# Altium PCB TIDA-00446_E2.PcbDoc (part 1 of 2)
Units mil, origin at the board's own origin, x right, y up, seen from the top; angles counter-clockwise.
Board outline 1780.03 x 5400.03 mil, 4 copper layers (Top Layer, GND, PWR, Bottom Layer), stack 79.834 mil thick; 192 components, 100 nets, 515 pads, 129 vias.
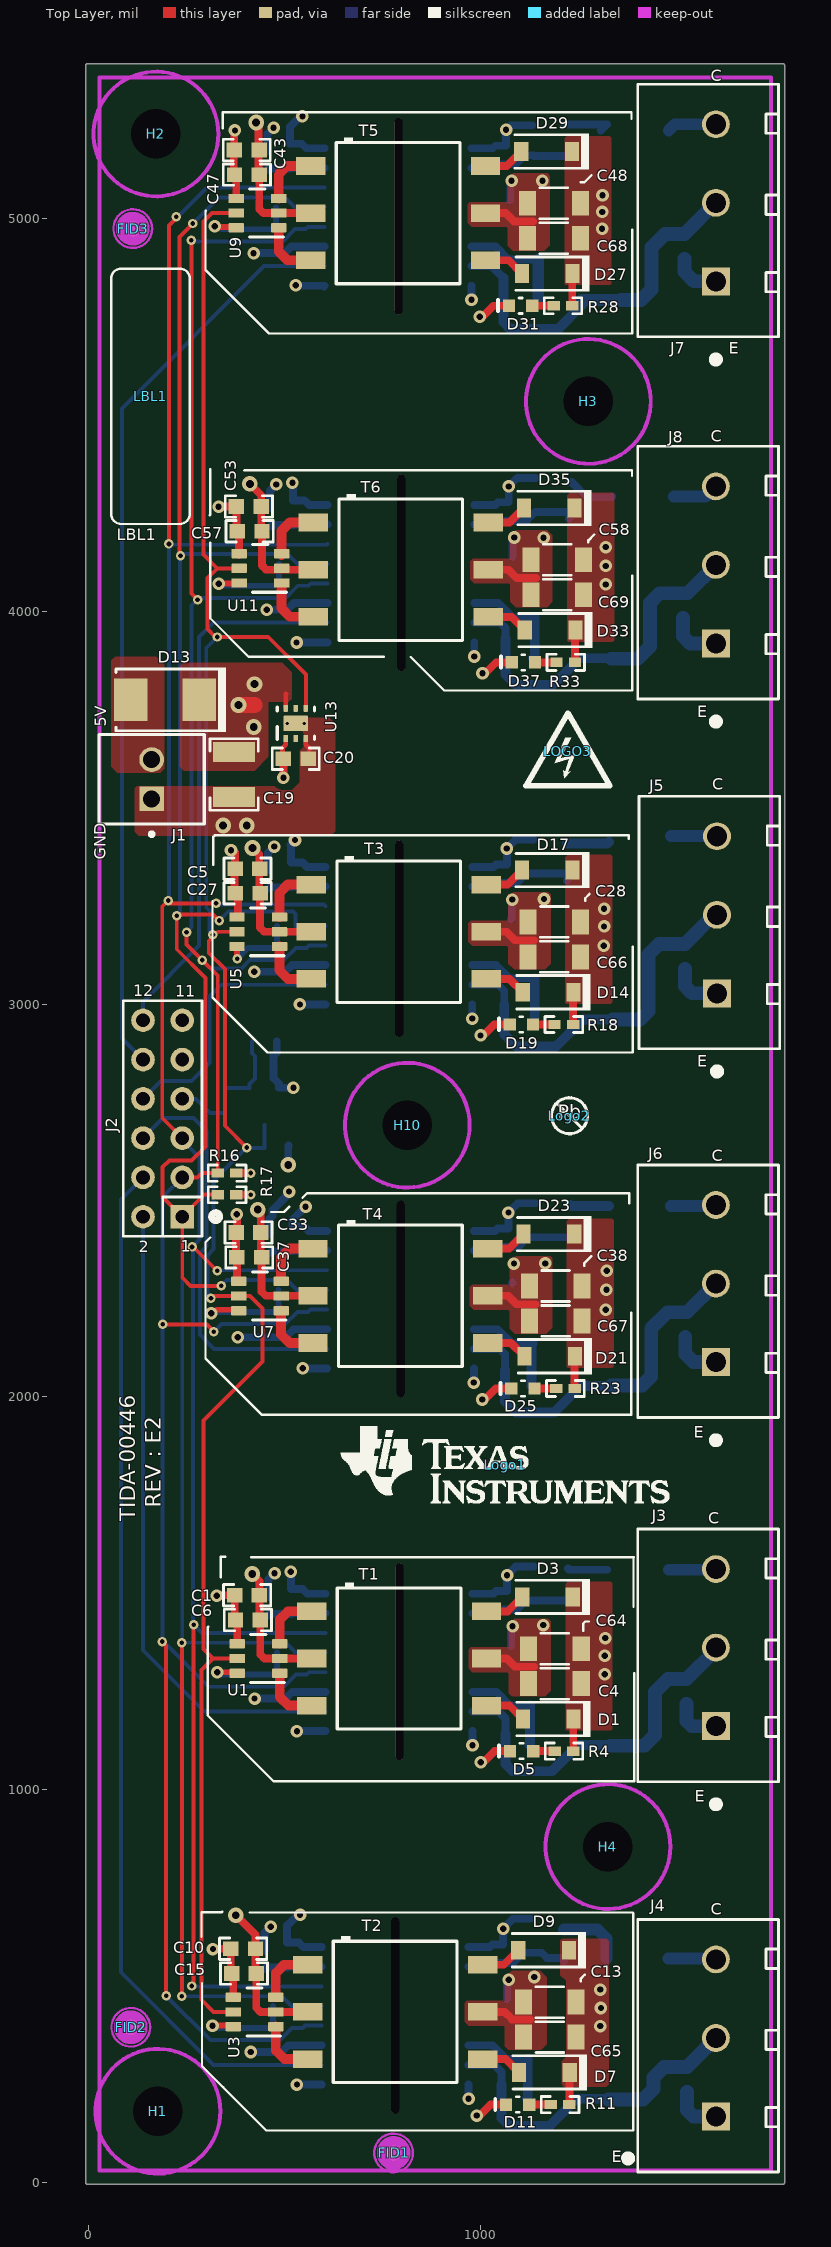
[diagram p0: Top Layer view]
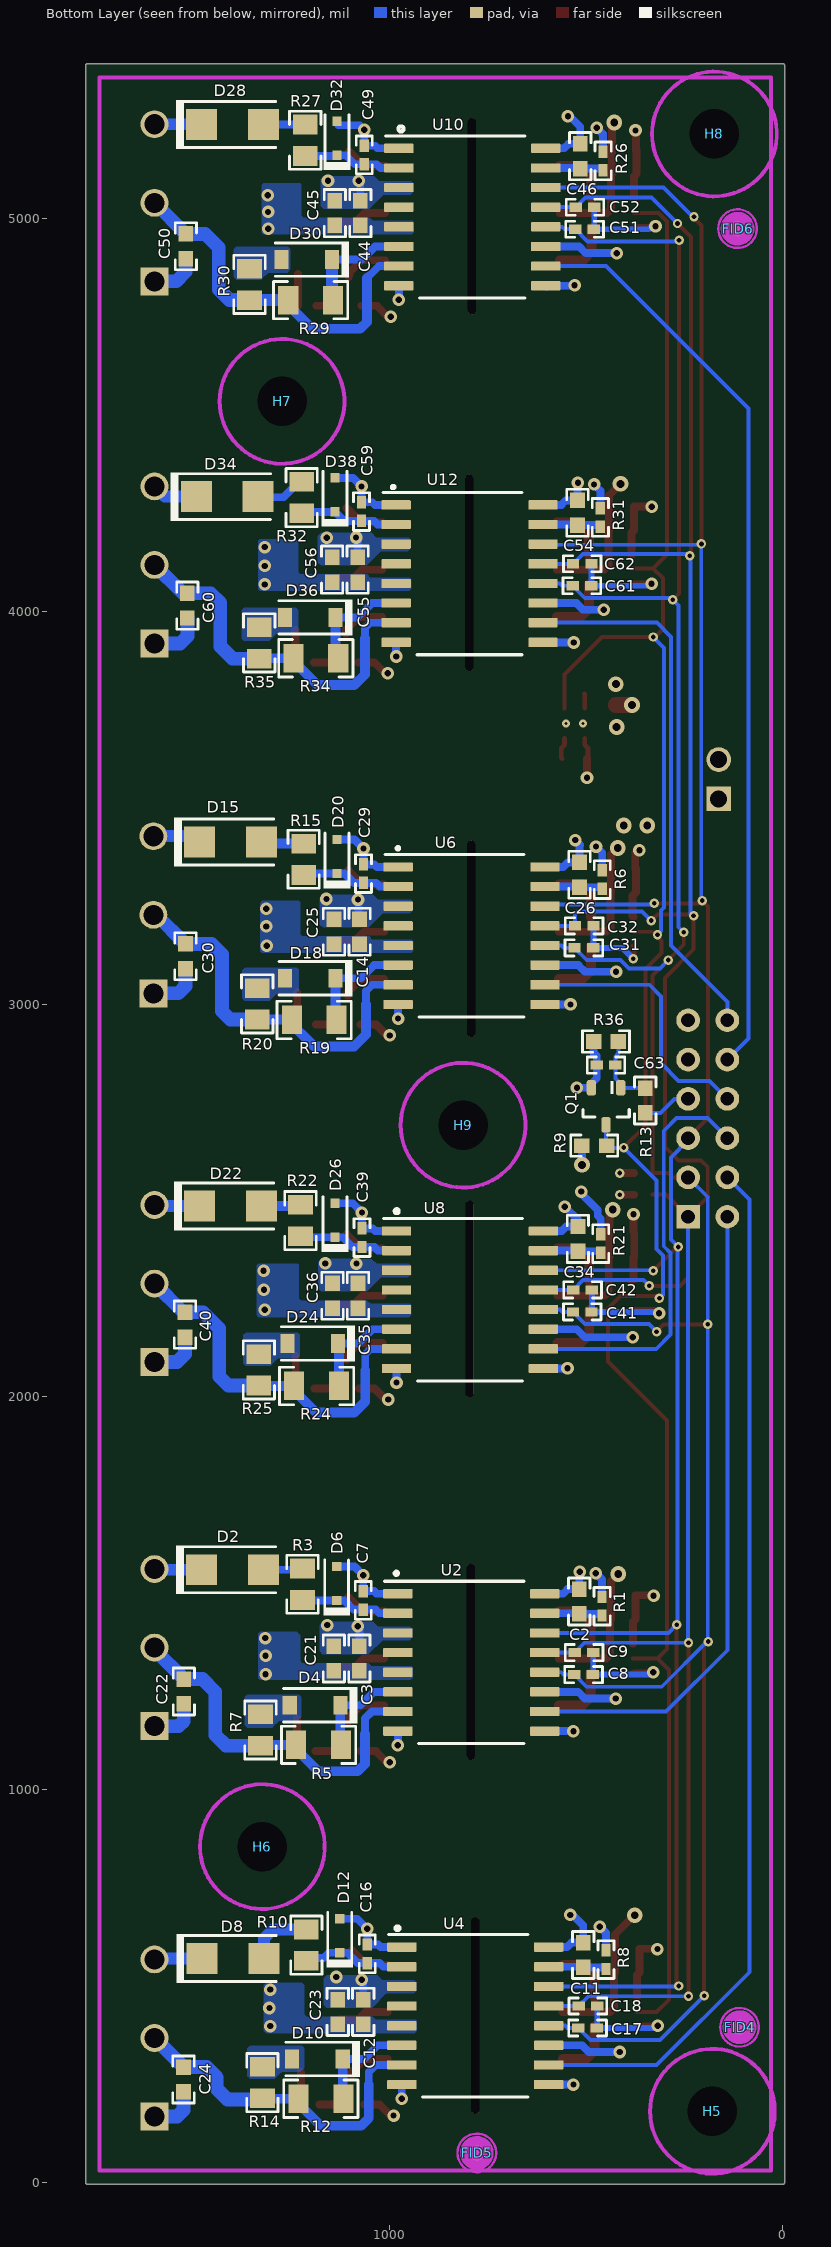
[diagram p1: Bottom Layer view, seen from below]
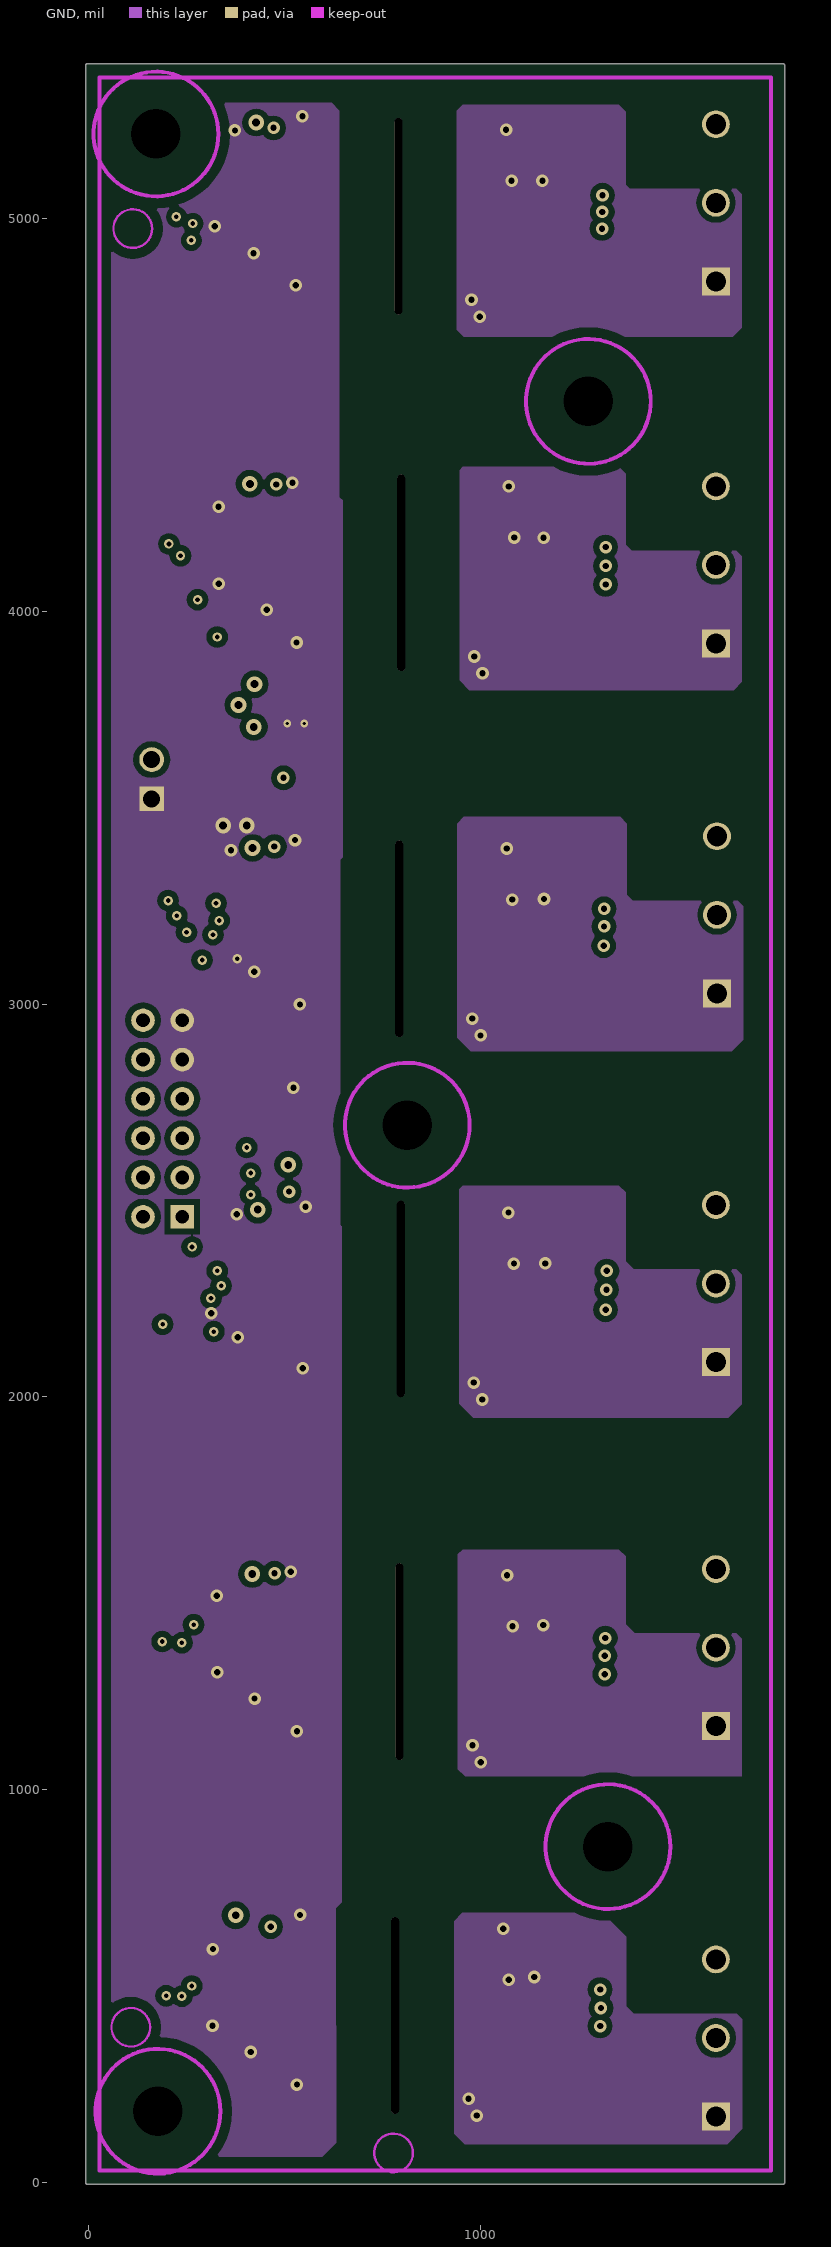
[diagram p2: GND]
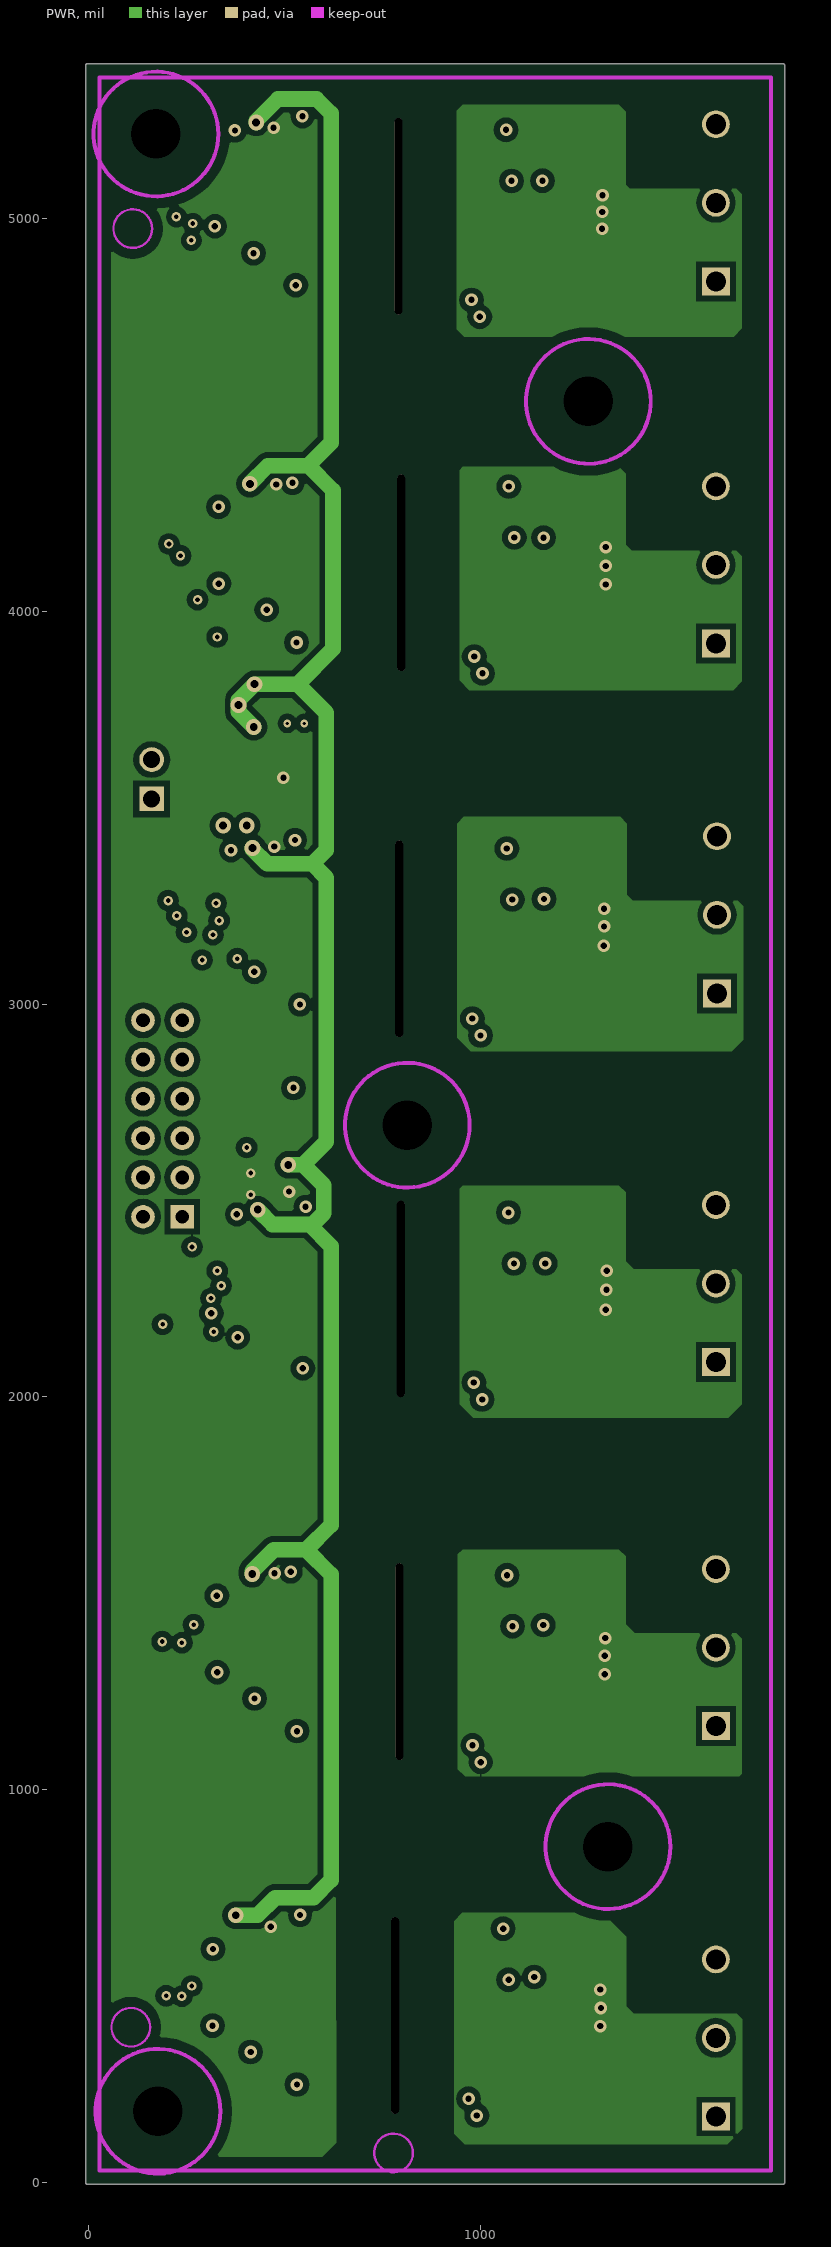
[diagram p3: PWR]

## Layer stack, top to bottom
Top Solder: solder mask 0.4, Solder Resist, Dk 3.5
Top Layer: signal copper 1.4
Dielectric1: core 59.2, FR-4, Dk 4.8
GND: signal copper 1.417
Dielectric2: prepreg 5, Dk 4.2
PWR: signal copper 1.417
Dielectric3: core 10, Dk 4.2
Bottom Layer: signal copper 1.4
Bottom Solder: solder mask 0.4, Solder Resist, Dk 3.5

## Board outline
-6.01,0 -6.01,5390 cw(c-1,5390) -1,5395.02 1769,5395.02 cw(c1769,5390) 1774.01,5390 1774.01,0 cw(c1769,0) 1769,-5.01 0,-5.01 cw(c0,0) -0.5,-4.99 cw(c-1,0)

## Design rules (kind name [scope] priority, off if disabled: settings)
AcuteAngle [All] p1: minimum=4.50000000000000E+0001 checktracksonly=FALSE
AssemblyTestPointUsage [All] p1: valid=2
Clearance Clearance_MTG_COPPER [InPadClass('MTG') vs InPolygon] p1: gap=40
Clearance Clearance_keepout [IsKeepOut vs InPolygon] p2: gap=25
Clearance "shape to all" [InPolygon] p3: gap=15
Clearance "Shape to Shape" [InPolygon vs InPolygon] p4: gap=20
Clearance Clearance_Boardedge_poly [OnCopper and InPolygon vs IsKeepOut] p5: gap=15
Clearance "SMD to Via" [IsSMTPin vs IsVia] p6: gap=8
Clearance "Clearance_via_thr pin" [IsVia vs IsThruPin] p7: gap=8
Clearance "Clearance_pad _class" [InPadClass('u12,u4,u5')] p8: gap=7.8
Clearance [All] p9: gap=8
DiffPairsRouting DiffPair_DiffPairsRouting [InDifferentialPair ('kan')] p1: maxlimit=10 minlimit=10 mostfreqgap=10 toplayer_minwidth=15 toplayer_maxwidth=15 toplayer_prefwidth=15 midlayer1_minwidth=15 midlayer1_maxwidth=15 midlayer1_prefwidth=15 midlayer2_minwidth=15 midlayer2_maxwidth=15 midlayer2_prefwidth=15 bottomlayer_minwidth=15 bottomlayer_maxwidth=15 bottomlayer_prefwidth=15 maxuncoupledlength=500
DiffPairsRouting DiffPair_DiffPairsRouting_1 [InDifferentialPair ('kan')] p2: maxlimit=10 minlimit=10 mostfreqgap=10 toplayer_minwidth=15 toplayer_maxwidth=15 toplayer_prefwidth=15 midlayer1_minwidth=15 midlayer1_maxwidth=15 midlayer1_prefwidth=15 midlayer2_minwidth=15 midlayer2_maxwidth=15 midlayer2_prefwidth=15 bottomlayer_minwidth=15 bottomlayer_maxwidth=15 bottomlayer_prefwidth=15 maxuncoupledlength=500
DiffPairsRouting [All] p3: maxlimit=100 minlimit=10 mostfreqgap=10 toplayer_minwidth=15 toplayer_maxwidth=15 toplayer_prefwidth=15 midlayer1_minwidth=15 midlayer1_maxwidth=15 midlayer1_prefwidth=15 midlayer2_minwidth=15 midlayer2_maxwidth=15 midlayer2_prefwidth=15 bottomlayer_minwidth=15 bottomlayer_maxwidth=15 bottomlayer_prefwidth=15 maxuncoupledlength=1000
FabricationTestPointUsage TestPointUsage [All] p1: valid=2 allowmultiple=FALSE
FabricationTestpoint Testpoint [All] p1: side=3 testpointundercomponent=TRUE minsize=40 maxsize=100 preferedsize=60 minholesize=0 maxholesize=40 preferedholesize=32 testpointgrid=1 allowsidetop=TRUE allowsidebottom=TRUE usegrid=TRUE gridtolerance=0.01
FanoutControl Fanout_LCC [IsLCC] p1: bgadir=Out bgaviamode=Centered fanoutstyle=Auto fanoutdirection=Alternating viagrid=1 // Fanout_LCC (Default Rule)
FanoutControl Fanout_BGA [IsBGA] p2: bgadir=Out bgaviamode=Centered fanoutstyle=Auto fanoutdirection=Alternating viagrid=1 // Fanout_BGA (Default Rule)
FanoutControl Fanout_Default [All] p4: bgadir=Out bgaviamode=Centered fanoutstyle=Auto fanoutdirection=Alternating viagrid=1 // Fanout_Default (Default Rule)
FanoutControl Fanout_Small [(CompPinCount < 5)] p5: bgadir=Out bgaviamode=Centered fanoutstyle=Auto fanoutdirection=OutThenIn viagrid=1 // Fanout_Small (Default Rule)
HoleSize [All] p1: absolutevalues=TRUE maxlimit=500 minlimit=7 maxpercent=80.000 minpercent=20.000
MatchedLengths DiffPair_MatchedLengths [InDifferentialPair ('kan')] p1: tolerance=1000 checknetsindiffpair=TRUE checkdiffpairvsdiffpair=TRUE checkothers=TRUE
MatchedLengths DiffPair_MatchedLengths_1 [InDifferentialPair ('kan')] p2: tolerance=1000 checknetsindiffpair=TRUE checkdiffpairvsdiffpair=TRUE checkothers=TRUE
MinimumAnnularRing [All] p1: minimumring=5
MinimumAnnularRing MinimumAnnularRing_ThermalPadVias [IsVia and InAnyComponent] p2: minimumring=5.91
MinimumSolderMaskSliver MinimumSolderMaskSliver_Logo [InComponentClass('Logo') vs InComponentClass('Logo')] p1: minsoldermaskwidth=0.7
MinimumSolderMaskSliver [All] p2: minsoldermaskwidth=3.94
PlaneClearance [All] p1: clearance=15
PlaneConnect [All] p1: planeconnectstyle=Direct reliefexpansion=10 reliefentries=4 reliefconductorwidth=10 reliefairgap=10
PolygonConnect [All] p1: connectstyle=Direct reliefconductorwidth=10 reliefentries=4 polygonreliefangle="90 Angle" airgapwidth=10
RoutingVias RoutingVias_power [InNetClass('POWER')] p1: holewidth=16 width=32 viastyle="Through Hole" minholewidth=7.87 minwidth=19.68 maxholewidth=16 maxwidth=32
RoutingVias ThermalPadVias [IsVia and InAnyComponent] p2: holewidth=8 width=20 viastyle="Through Hole" minholewidth=7.87 minwidth=19 maxholewidth=12 maxwidth=24
RoutingVias [All] p3: holewidth=16 width=32 viastyle="Through Hole" minholewidth=12 minwidth=24 maxholewidth=20 maxwidth=40
SMDToCorner [All] p1: distance=30000
SilkToSilkClearance [All] p1: silktosilkclearance=5
SilkToSolderMaskClearance SilkscreenOverComponentPads [IsPad] p1: minsilkscreentomaskgap=5 clearancetoexposedcopper=TRUE
SolderMaskExpansion [All] p1: expansion=3
UnpouredPolygon [All] p1: allowunpoured=FALSE
Width Width_power [InNetClass('POWER')] p1: maxlimit=100 minlimit=8 preferedwidth=20
Width [All] p2: maxlimit=100 minlimit=10 preferedwidth=10 checkconnectedcopper=TRUE
15 further rules are at their usual default settings.

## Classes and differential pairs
component class Label: LBL1
component class TIDA-00446_E2_GateDriverPhaseU: C1 C2 C3 C4 C6 C7 C8 C9 C10 C11 C12 C13 C15 C16 C17 C18 C19 C20 C21 C22 C23 C24 C63 C64 C65 D1 D2 D3 D4 D5 D6 D7 D8 D9 D10 D11 D12 D13 J1 J2 J3 J4 Q1 R1 R3 R4 R5 R7 R8 R9 R10 R11 R12 R13 R14 R16 R17 R36 T1 T2 U1 U2 U3 U4 U13
component class FiducialMark: FID1 FID2 FID3 FID4 FID5 FID6
component class TIDA-00446_E2_TID_Hardware: FID1 FID2 FID3 FID4 FID5 FID6 H1 H2 H3 H4 H5 H6 H7 H8 H9 H10 LBL1 Logo1 Logo2 LOGO3 ZZ2 ZZ3 ZZ4
component class Logo: Logo1
component class AssemblyNote: ZZ2 ZZ3 ZZ4
component class Header: J2
component class TIDA-00446_E2_GateDriverPhaseV: C5 C14 C25 C26 C27 C28 C29 C30 C31 C32 C33 C34 C35 C36 C37 C38 C39 C40 C41 C42 C66 C67 D14 D15 D17 D18 D19 D20 D21 D22 D23 D24 D25 D26 J5 J6 R6 R15 R18 R19 R20 R21 R22 R23 R24 R25 T3 T4 U5 U6 U7 U8
component class TIDA-00446_E2_GateDriverPhaseW: C43 C44 C45 C46 C47 C48 C49 C50 C51 C52 C53 C54 C55 C56 C57 C58 C59 C60 C61 C62 C68 C69 D27 D28 D29 D30 D31 D32 D33 D34 D35 D36 D37 D38 J7 J8 R26 R27 R28 R29 R30 R31 R32 R33 R34 R35 T5 T6 U9 U10 U11 U12
component class "Mounting Holes": H1 H2 H3 H4 H10

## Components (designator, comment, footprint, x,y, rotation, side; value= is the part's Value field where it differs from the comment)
C1 "GRM188R71H104KA93D" 0603 405,1495 r0 top
C2 "GRM188R71H104KA93D" 0603 517,1479 r90 bottom
C3 "C1608X7R1V105K080AC" 0603 1077,1334 r90 bottom
C4 "C3216X7R1V106K160AC" 1206_190 1189,1270 r180 top
C5 "GRM188R71H104KA93D" 0603 406,3345 r0 top
C6 "GRM188C81A106MA73D" 0603 407,1432 r180 top
C7 "C1005X7R1H104K050BB" 0402 1067,1482 r90 bottom
C8 "GRM1555C1H220FA01D" 0402 506,1293 r180 bottom
C9 "GRM1555C1H220FA01D" 0402 505,1349 r180 bottom
C10 "GRM188R71H104KA93D" 0603 395,595 r0 top
C11 "GRM188R71H104KA93D" 0603 507,579 r90 bottom
C12 "C1608X7R1V105K080AC" 0603 1067,434 r90 bottom
C13 "C3216X7R1V106K160AC" 1206_190 1176,459 r180 top
C14 "C1608X7R1V105K080AC" 0603 1076.49,3184.51 r90 bottom
C15 "GRM188C81A106MA73D" 0603 397,532 r180 top
C16 "GRM155R71H221KA01D" 0402 1057,582 r90 bottom
C17 "GRM1555C1H220FA01D" 0402 496,393 r180 bottom
C18 "GRM1555C1H220FA01D" 0402 495,449 r180 bottom
C19 "GRM32ER61C476ME15L" 1210 372,3585 r270 top
C20 "C1608X7S1A475K080AC" 0603 529,3625 r0 top
C21 "GRM188R71H104KA93D" 0603 1142,1334 r90 bottom
C22 "GRM188R71H104KA93D" 0603 1524,1250 r270 bottom
C23 "GRM188R71H104KA93D" 0603 1132,434 r90 bottom
C24 "GRM188R71H104KA93D" 0603 1525,262 r270 bottom
C25 "GRM188R71H104KA93D" 0603 1141.49,3184.51 r90 bottom
C26 "GRM188R71H104KA93D" 0603 516.49,3329.51 r90 bottom
C27 "GRM188C81A106MA73D" 0603 406.49,3282.51 r180 top
C28 "C3216X7R1V106K160AC" 1206_190 1187.49,3209.51 r180 top
C29 "C1005X7R1H104K050BB" 0402 1066.49,3332.51 r90 bottom
C30 "GRM188R71H104KA93D" 0603 1520,3122 r270 bottom
C31 "GRM1555C1H220FA01D" 0402 505.49,3143.51 r180 bottom
C32 "GRM1555C1H220FA01D" 0402 504.49,3199.51 r180 bottom
C33 "GRM188R71H104KA93D" 0603 408.49,2418.51 r0 top
C34 "GRM188R71H104KA93D" 0603 520.49,2402.51 r90 bottom
C35 "C1608X7R1V105K080AC" 0603 1080.49,2257.51 r90 bottom
C36 "GRM188R71H104KA93D" 0603 1145.49,2257.51 r90 bottom
C37 "GRM188C81A106MA73D" 0603 410.49,2355.51 r180 top
C38 "C3216X7R1V106K160AC" 1206_190 1190.49,2282.51 r180 top
C39 "GRM155R71H221KA01D" 0402 1070.49,2405.51 r90 bottom
C40 "GRM188R71H104KA93D" 0603 1521,2184 r270 bottom
C41 "GRM1555C1H220FA01D" 0402 509.49,2216.51 r180 bottom
C42 "GRM1555C1H220FA01D" 0402 508.49,2272.51 r180 bottom
C43 "GRM188R71H104KA93D" 0603 404,5175 r0 top
C44 "C1608X7R1V105K080AC" 0603 1074.49,5014.51 r90 bottom
C45 "GRM188R71H104KA93D" 0603 1139.49,5014.51 r90 bottom
C46 "GRM188R71H104KA93D" 0603 514.49,5159.51 r90 bottom
C47 "GRM188C81A106MA73D" 0603 404.49,5112.51 r180 top
C48 "C3216X7R1V106K160AC" 1206_190 1186.49,5039.51 r180 top
C49 "C1005X7R1H104K050BB" 0402 1064.49,5162.51 r90 bottom
C50 "GRM188R71H104KA93D" 0603 1519,4930 r270 bottom
C51 "GRM1555C1H220FA01D" 0402 503.49,4973.51 r180 bottom
C52 "GRM1555C1H220FA01D" 0402 502.49,5029.51 r180 bottom
C53 "GRM188R71H104KA93D" 0603 409.49,4267.51 r0 top
C54 "GRM188R71H104KA93D" 0603 521.49,4251.51 r90 bottom
C55 "C1608X7R1V105K080AC" 0603 1081.49,4106.51 r90 bottom
C56 "GRM188R71H104KA93D" 0603 1146.49,4106.51 r90 bottom
C57 "GRM188C81A106MA73D" 0603 411.49,4204.51 r180 top
C58 "C3216X7R1V106K160AC" 1206_190 1194.49,4131.51 r180 top
C59 "GRM155R71H221KA01D" 0402 1071.49,4254.51 r90 bottom
C60 "GRM188R71H104KA93D" 0603 1515,4015 r270 bottom
C61 "GRM1555C1H220FA01D" 0402 510.49,4065.51 r180 bottom
C62 "GRM1555C1H220FA01D" 0402 509.49,4121.51 r180 bottom
C63 "GRM1555C1H220FA01D" 0402 449,2845 r0 bottom
C64 "C3216X7R1V106K160AC" 1206_190 1189,1359 r180 top
C65 "C3216X7R1V106K160AC" 1206_190 1176,370 r180 top
C66 "C3216X7R1V106K160AC" 1206_190 1187.49,3120.51 r180 top
C67 "C3216X7R1V106K160AC" 1206_190 1190.49,2193.51 r180 top
C68 "C3216X7R1V106K160AC" 1206_190 1186.49,4950.51 r180 top
C69 "C3216X7R1V106K160AC" 1206_190 1194.49,4042.51 r180 top
D1 "MBR0540T1G" SOD-123 1172,1180 r180 top
D2 "STTH112A" SMA 1400,1560 r180 bottom
D3 "MBR0540T1G" SOD-123 1170,1491 r180 top
D4 "1N5819HW-7-F" SOD-123 1190,1215 r0 bottom
D5 "LG L29K-G2J1-24-Z" "LG L29K_GREEN" 1104,1098 r180 top
D6 "BAT54WS-7-F" sod-323 1135,1525 r90 bottom
D7 "MBR0540T1G" SOD-123 1162,280 r180 top
D8 "STTH112A" SMA 1399,570 r180 bottom
D9 "MBR0540T1G" SOD-123 1160,591 r180 top
D10 "1N5819HW-7-F" SOD-123 1184,314 r0 bottom
D11 "LG L29K-G2J1-24-Z" "LG L29K_GREEN" 1094,198 r180 top
D12 "BAT54WS-7-F" sod-323 1127,628 r90 bottom
D13 "B340LB-13-F" SMB 196,3775 r180 top
D14 "MBR0540T1G" SOD-123 1171.49,3030.51 r180 top
D15 "STTH112A" SMA 1405,3413 r180 bottom
D17 "MBR0540T1G" SOD-123 1169.49,3341.51 r180 top
D18 "1N5819HW-7-F" SOD-123 1202,3066 r0 bottom
D19 "LG L29K-G2J1-24-Z" "LG L29K_GREEN" 1103.49,2948.51 r180 top
D20 "BAT54WS-7-F" sod-323 1134,3376 r90 bottom
D21 "MBR0540T1G" SOD-123 1175.49,2103.51 r180 top
D22 "STTH112A" SMA 1405,2486 r180 bottom
D23 "MBR0540T1G" SOD-123 1173.49,2414.51 r180 top
D24 "1N5819HW-7-F" SOD-123 1196,2136 r0 bottom
D25 "LG L29K-G2J1-24-Z" "LG L29K_GREEN" 1107.49,2021.51 r180 top
D26 "BAT54WS-7-F" sod-323 1139,2450 r90 bottom
D27 "MBR0540T1G" SOD-123 1169.49,4860.51 r180 top
D28 "STTH112A" SMA 1399.87,5240 r180 bottom
D29 "MBR0540T1G" SOD-123 1167.49,5171.51 r180 top
D30 "1N5819HW-7-F" SOD-123 1211,4896 r0 bottom
D31 "LG L29K-G2J1-24-Z" "LG L29K_GREEN" 1101.49,4778.51 r180 top
D32 "BAT54WS-7-F" sod-323 1134,5205 r90 bottom
D33 "MBR0540T1G" SOD-123 1176.49,3952.51 r180 top
D34 "STTH112A" SMA 1413.49,4292.51 r180 bottom
D35 "MBR0540T1G" SOD-123 1174.49,4263.51 r180 top
D36 "1N5819HW-7-F" SOD-123 1202,3985 r0 bottom
D37 "LG L29K-G2J1-24-Z" "LG L29K_GREEN" 1108.49,3870.51 r180 top
D38 "BAT54WS-7-F" sod-323 1139,4297 r90 bottom
FID1 "Fiducial" Fiducial10-20 778,75 r90 top
FID2 "Fiducial" Fiducial10-20 109,395 r90 top
FID3 "Fiducial" Fiducial10-20 114,4975 r90 top
FID4 "Fiducial" Fiducial10-20 109,395 r90 bottom
FID5 "Fiducial" Fiducial10-20 778,75 r90 bottom
FID6 "Fiducial" Fiducial10-20 114,4975 r90 bottom
H1 "NY PMS 440 0025 PH" "NY PMS 440 0025 PH"#1 178,181 r0 top
H2 "NY PMS 440 0025 PH" "NY PMS 440 0025 PH"#2 173,5221 r0 top
H3 "NY PMS 440 0025 PH" "NY PMS 440 0025 PH"#1 1274,4535 r0 top
H4 "NY PMS 440 0025 PH" "NY PMS 440 0025 PH"#1 1324,855 r0 top
H5 "1902C" Keystone_1902C 178,181 r180 bottom
H6 "1902C" Keystone_1902C 1324,855 r180 bottom
H7 "1902C" Keystone_1902C 1274,4535 r180 bottom
H8 "1902C" Keystone_1902C 173,5216 r180 bottom
H9 "1902C" Keystone_1902C 813,2692 r180 bottom
H10 "NY PMS 440 0025 PH" "NY PMS 440 0025 PH"#1 813,2692 r0 top
J1 "282834-2" TEC_282834-2 162,3573 r90 top
J2 "87227-6" CONN_87227-6 190,2709 r90 top
J3 "OSTTA034163" On-Shore_OSTTA034163 1579,1342 r90 top
J4 "OSTTA034163" On-Shore_OSTTA034163 1579,348 r90 top
J5 "OSTTA034163" On-Shore_OSTTA034163 1582,3208 r90 top
J6 "OSTTA034163" On-Shore_OSTTA034163 1579,2269 r90 top
J7 "OSTTA034163" On-Shore_OSTTA034163 1579,5021 r90 top
J8 "OSTTA034163" On-Shore_OSTTA034163 1579,4099 r90 top
LBL1 "Size: 0.65\" x 0.20 \"" Label_650x200 159,4548 r90 top
Logo1 "Texas Instruments" TI_Stacked_Overlay_Small 1062,1827 r0 top
Logo2 "Pb-Free Symbol" Pb-Free_Overlay_Small 1226,2716 r0 top
LOGO3 "DANGER HIGH VOLTAGE" IEC_HighVoltage_Small 1222,3644 r0 top
Q1 "BC848CLT1G" SOT-23 449,2740 r270 bottom
R1 "CRCW040210R0JNED" 0402 459,1467 r270 bottom
R3 "CRCW08051K00JNEA" 0805_HV 1222,1523 r90 bottom
R4 "CRCW04024K99FKED" 0402 1212,1098 r0 top
R5 "RPC1206JT4R70" 1206 1181,1114 r0 bottom
R6 "CRCW040210R0JNED" 0402 458.49,3317.51 r270 bottom
R7 "RPC0805JT4R70" 0805_HV 1329,1152 r270 bottom
R8 "RC0402JR-070RL" 0402 449,567 r270 bottom
R9 "CRCW060322K0JNEA" 0603 479,2640 r0 bottom
R10 "CRCW08051K00JNEA" 0805_HV 1212,604 r90 bottom
R11 "CRCW04024K99FKED" 0402 1202,198 r0 top
R12 "RPC1206JT4R70" 1206 1175,213 r0 bottom
R13 "CRCW0603100KJNEA" 0603 349,2755 r90 bottom
R14 "RPC0805JT4R70" 0805_HV 1324,254 r270 bottom
R15 "CRCW08051K00JNEA" 0805_HV 1219,3369 r90 bottom
R16 "CRCW040210R0JNED" 0402 354,2570 r0 top
R17 "CRCW040210R0JNED" 0402 354,2515 r0 top
R18 "CRCW04024K99FKED" 0402 1211.49,2948.51 r0 top
R19 "RPC1206JT4R70" 1206 1192,2960 r0 bottom
R20 "RPC0805JT4R70" 0805_HV 1337,3001 r270 bottom
R21 "RC0402JR-070RL" 0402 462.49,2390.51 r270 bottom
R22 "CRCW08051K00JNEA" 0805_HV 1227,2449 r90 bottom
R23 "CRCW04024K99FKED" 0402 1215.49,2021.51 r0 top
R24 "RPC1206JT4R70" 1206 1186,2028 r0 bottom
R25 "RPC0805JT4R70" 0805_HV 1333,2069 r270 bottom
R26 "CRCW040210R0JNED" 0402 456.49,5147.51 r270 bottom
R27 "CRCW08051K00JNEA" 0805_HV 1215,5200 r90 bottom
R28 "CRCW04024K99FKED" 0402 1209.49,4778.51 r0 top
R29 "RPC1206JT4R70" 1206 1201,4793 r0 bottom
R30 "RPC0805JT4R70" 0805_HV 1357,4833 r270 bottom
R31 "RC0402JR-070RL" 0402 463.49,4239.51 r270 bottom
R32 "CRCW08051K00JNEA" 0805_HV 1224,4290 r90 bottom
R33 "CRCW04024K99FKED" 0402 1216.49,3870.51 r0 top
R34 "RPC1206JT4R70" 1206 1188,3881 r0 bottom
R35 "RPC0805JT4R70" 0805_HV 1332,3920 r270 bottom
R36 "CRCW0603100KJNEA" 0603 449,2905 r180 bottom
T1 "750342879" Wurth_750342879 792,1334 r0 top
T2 "750342879" Wurth_750342879 782,434 r0 top
T3 "750342879" Wurth_750342879 791.49,3184.51 r0 top
T4 "750342879" Wurth_750342879 795.49,2257.51 r0 top
T5 "750342879" Wurth_750342879 789.49,5014.51 r0 top
T6 "750342879" Wurth_750342879 796.49,4106.51 r0 top
U1 "SN6505BDBVR" DBV0006A_N 434,1334 r180 top
U2 "ISO5851DWR" DW0016B_N 792,1324 r180 bottom
U3 "SN6505BDBVR" DBV0006A_N 424,434 r180 top
U4 "ISO5851DWR" DW0016B_N 782,424 r180 bottom
U5 "SN6505BDBVR" DBV0006A_N 433.49,3184.51 r180 top
U6 "ISO5851DWR" DW0016B_N 791.49,3174.51 r180 bottom
U7 "SN6505BDBVR" DBV0006A_N 438,2257 r180 top
U8 "ISO5851DWR" DW0016B_N 795.49,2247.51 r180 bottom
U9 "SN6505BDBVR" DBV0006A_N 431.49,5014.51 r180 top
U10 "ISO5851DWR" DW0016B_N 789.49,5004.51 r180 bottom
U11 "SN6505BDBVR" DBV0006A_N 439,4110 r180 top
U12 "ISO5851DWR" DW0016B_N 796.49,4096.51 r180 bottom
U13 "TPS70633DRVR" DRV0006A 529,3715 r90 top
ZZ2 "These assemblies are ESD sensitive, ESD precautions shall be observed." AssemblyNote 715,6461 r0 top
ZZ3 "These assemblies must be clean and free from flux and all contaminants. Use of no clean flux is not acceptable." AssemblyNote 715,6376 r0 top
ZZ4 "These assemblies must comply with workmanship standards IPC-A-610 Class 2, unless otherwise specified." AssemblyNote 715,6301 r0 top

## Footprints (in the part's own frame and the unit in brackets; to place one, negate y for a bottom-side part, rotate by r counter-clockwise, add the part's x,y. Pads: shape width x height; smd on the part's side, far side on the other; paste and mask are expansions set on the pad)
0402 [mm] "0402 from SM-752 data"
  rect 0.8x0.6 smd: 1(-0.6,0) 2(0.6,0)
  silkscreen extent -1.22,-0.52 1.22,0.52, body extent -0.55,-0.3 0.55,0.3, height 0.6
0603 [mm] "0603 from SM-752 data"
  rect 1x0.95 smd: 1(-0.8,0) 2(0.8,0)
  silkscreen extent -1.52,-0.69 1.52,0.69, body extent -0.87,-0.47 0.87,0.47, height 0.85
0805_HV [mil] "0805 with 30mil clearance between pads"
  rect 50x63 smd: 1(-40,0) 2(40,0)
  silkscreen extent -74,-40 74,40, body extent -43,-29 43,29, height 57
1206 [mm] "1206 from SM-752 data"
  rect 1.3x1.85 smd: 1(-1.45,0) 2(1.45,0)
  silkscreen extent -2.4,-1.21 2.4,1.21, body extent -1.7,-0.9 1.7,0.9, height 1.35
1206_190 [mm] "1206_190"
  rect 1.1x1.6 smd: 1(-1.7,0) 2(1.7,0)
  silkscreen extent -0.9,-1 0.9,1, body extent -1.75,-0.95 1.75,0.95, height 1.9
1210 [mm] "1210 from SM-752 data"
  rect 1.3x2.7 smd: 1(-1.45,0) 2(1.45,0)
  silkscreen extent -2.32,-1.57 2.32,1.57, body extent -1.7,-1.35 1.7,1.35, height 1.35
AssemblyNote [mil] "Assembly Note"
CONN_87227-6 [mil] "TE Connectivity"
  rect 60x60 hole 35: 1(-250,-50)
  round 60 hole 35: 2(-250,50) 3(-150,-50) 4(-150,50) 5(-50,-50) 6(-50,50) 7(50,-50) 8(50,50) 9(150,-50) 10(150,50) 11(250,-50) 12(250,50)
  silkscreen extent -300,-145 300,100, body extent -300,-99 300,99, height 408
DBV0006A_N [mm] "SOT23, 6-Leads, Body 2.9x1.6mm, Pitch 0.95mm, Lead Span 2.8mm, IPC Medium Density"
  rrect17% 1x0.6 smd: 1(-1.375,0.95) 2(-1.375,0) 3(-1.375,-0.95) 4(1.375,-0.95) 5(1.375,0) 6(1.375,0.95)
  silkscreen extent -1.68,-1.55 0.5,1.55, body extent -1.42,-1.46 1.42,1.46, height 1.12
DRV0006A [mm] "SON, 6-Leads, Body 2x2mm, Pitch 0.65mm, Thermal Pad 1.6x1mm, TI Recommended"
  rrect33% 0.45x0.3 smd: 1(-0.975,0.65) 2(-0.975,0) 3(-0.975,-0.65) 4(0.975,-0.65) 5(0.975,0) 6(0.975,0.65)
  rrect10% 1x1.6 smd paste-0.5: 7(0,0)
  silkscreen extent -1.05,-1.2 1.05,1.2, body extent -1.05,-1.05 1.05,1.05, height 0.81
DW0016B_N [mm] "SOIC, 16-Leads, Body 10.5x7.6mm, Pitch 1.27mm, IPC Medium Density"
  rrect17% 1.9x0.6 smd: 1(-4.75,4.445) 2(-4.75,3.175) 3(-4.75,1.905) 4(-4.75,0.635) 5(-4.75,-0.635) 6(-4.75,-1.905) 7(-4.75,-3.175) 8(-4.75,-4.445) 9(4.75,-4.445) 10(4.75,-3.175) 11(4.75,-1.905) 12(4.75,-0.635) 13(4.75,0.635) 14(4.75,1.905) 15(4.75,3.175) 16(4.75,4.445)
  silkscreen extent -5.6,-5.25 3.4,5.25, body extent -5.17,-5.15 5.17,5.15, height 2.59
Fiducial10-20 [mm]
  round 1 smd mask+0.5: 1(0,0)
  Top Layer keep-out circle w1.178: c0,0 r0.5
IEC_HighVoltage_Small [mil]
  silkscreen extent -107,-88 107,97
Keystone_1902C [mil] "Hex Standoff, 4-40 threaded, nylon"
  round 1 on Mech4: 0(0,0)
  body extent -145,-126 146,126, height 501
Label_650x200 [mil] "Thermal Transfer Label"
  round 1 on Mech13: 0(0,0)
  silkscreen extent -325,-100 325,100, body extent -326,-101 326,101, height 1
"LG L29K_GREEN" [mm] "OSRAM"
  rect 0.8x0.8 smd paste-0.4: 1(-0.75,0) 2(0.75,0)
  silkscreen extent -0.1,-0.5 1.45,0.5, body extent -0.9,-0.45 0.9,0.45, height 0.67
"NY PMS 440 0025 PH"#1 [mil] "4-40 nylon screw and mounting hole"
  round 120 hole 125.98 unplated mask+10: 1(0,0)
  body extent -130,-130 130,130, height 106
"NY PMS 440 0025 PH"#2 [mil] "4-40 nylon screw and mounting hole"
  round 120 hole 125.98 unplated mask+10: 1(0,-5)
  body extent -130,-130 130,130, height 106
On-Shore_OSTTA034163 [mm] "TERM BLOCK 3x1, 5.08mm, TH"
  rect 1.8x1.8 hole 1.3: 1(-4.58,-0.5)
  round 1.8 hole 1.3 paste+0: 2(0.5,-0.5) 3(5.58,-0.5)
  silkscreen extent -9.73,-4.55 8.17,4.55, body extent -8.22,-4.6 8.22,4.6, height 13
Pb-Free_Overlay_Small [mil]
  silkscreen extent -46,-46 46,46
SMA [mm] "Molded Diode, 2-Leads, Body 4.3x2.6mm, IPC Medium Density, based on OnSemi component dimensions and land pattern"
  rect 2x2 smd: 1(-2,0) 2(2,0)
  silkscreen extent -3.66,-1.57 2.79,1.57, body extent -2.6,-1.3 2.6,1.3, height 2.42
SMB [mil] "Molded Diode, 2-Leads, Body 5.4x3.6mm, IPC Medium Density, based on OnSemi component dimensions"
  rect 85x107.99 smd: 1(-87.01,0) 2(87.01,0)
  silkscreen extent -155,-82 125,82, body extent -106,-71 106,71, height 91
SOD-123 [mm] "On Semi recommended land pattern"
  rect 0.915x1.22 smd: 1(-1.637,0) 2(1.637,0)
  silkscreen extent -2.74,-1.17 2.03,1.17, body extent -1.93,-0.9 1.93,0.9, height 1.35
sod-323 [mm] "NXP recommended land pattern"
  rect 0.6x0.6 smd paste-0.05: 1(-1.1,0) 2(1.1,0)
  silkscreen extent -2.06,-0.86 1.53,0.86, body extent -1.3,-0.67 1.3,0.68, height 1.1
SOT-23 [mm] "SOT23, 3-Leads, Body 2.9x1.3mm, Pitch 0.95mm, Lead Span 2.5mm, IPC Medium Density"
  rrect50% 1x0.6 smd: 1(-1.2,0.95) 2(-1.2,-0.95) 3(1.2,0)
  silkscreen extent -1.62,-1.5 0.7,1.5, body extent -1.16,-1.45 1.21,1.45, height 1
TEC_282834-2 [mm] "TEC"
  rect 1.6x1.6 hole 1.1: 1(-1.27,0)
  round 1.6 hole 1.1: 2(1.27,0)
  silkscreen extent -3.66,-3.4 2.9,3.4, body extent -2.77,-3.25 2.77,3.25, height 10.01
TI_Stacked_Overlay_Small [mil]
  silkscreen extent -418,-98 418,98
Wurth_750342879 [mm] "SMD, 6-Leads, Body 9.14x8mm, Pitch 3.05mm"
  rect 1.9x1.14 smd: 1(-5.655,3.05) 2(-5.655,0) 3(-5.655,-3.05) 4(5.655,-3.05) 5(5.655,0) 6(5.655,3.05)
  silkscreen extent -4,-4.57 4,4.9, body extent -6.35,-4.57 6.35,4.57, height 7.83

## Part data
C1 C2 C5 C10 C11 C21 C22 C23 C24 C25 C26 C30 C33 C34 C36 C40 C43 C45 C46 C50 C53 C54 C56 C60: "CAP, CERM, 0.1 µF, 50 V, +/- 10%, X7R, 0603"
C3 C12 C14 C35 C44 C55: "CAP, CERM, 1 µF, 30 V, +/- 10%, X7R, 0603"
C4 C13 C28 C38 C48 C58 C64 C65 C66 C67 C68 C69: "CAP, CERM, 10 µF, 35 V, +/- 10%, X7R, 1206_190"
C6 C15 C27 C37 C47 C57: "CAP, CERM, 10 µF, 10 V, +/- 20%, X6S, 0603"
C7 C29 C49: library part GRM155R71H221KA01D, "CAP, CERM, 220 pF, 50 V, +/- 10%, X7R, 0402"
C8 C9 C17 C18 C31 C32 C41 C42 C51 C52 C61 C62 C63: "CAP, CERM, 22 pF, 50 V, +/- 1%, C0G/NP0, 0402"
C16 C39 C59: "CAP, CERM, 220 pF, 50 V, +/- 10%, X7R, 0402"
C19: "CAP, CERM, 47 µF, 16 V, +/- 20%, X5R, 1210"
C20: "CAP, CERM, 4.7 µF, 10 V, +/- 10%, X7S, 0603"
D1 D3 D7 D9 D14 D17 D21 D23 D27 D29 D33 D35: "Diode, Schottky, 40 V, 0.5 A, SOD-123"
D2 D8 D15 D22 D28 D34: "Diode, Ultrafast, 1200 V, 1 A, SMA"
D4 D10 D18 D24 D30 D36: "Diode, Schottky, 40 V, 1 A, SOD-123"
D5 D11 D19 D25 D31 D37: "LED, Green, SMD"
D6 D12 D20 D26 D32 D38: "Diode, Schottky, 30 V, 0.2 A, SOD-323"
D13: "Diode, Schottky, 40 V, 3 A, SMB"
FID1 FID2 FID3 FID4 FID5 FID6: "Fiducial mark.  There is nothing to buy or mount."
H1 H2 H3 H4 H10: "Machine Screw, Round, #4-40 x 1/4, Nylon, Philips panhead"
H5 H6 H7 H8 H9: "Standoff, Hex, 0.5\"L #4-40 Nylon"
J1: "Terminal Block, 2x1, 2.54mm, TH"
J2: "Header, 100mil, 6x2, Gold, TH"
J3 J4 J5 J6 J7 J8: "Terminal Block, 3x1, 5.08 mm, TH"
LBL1: library part THT-14-423-10, "Thermal Transfer Printable Labels, 0.650\" W x 0.200\" H - 10,000 per roll"
Logo1: library part TI_Logo, "Texas Instrument Corporate Signature"
Logo2: library part Pb-Free
LOGO3: library part IEC_HighVoltage, "IEC 61010-1 High Voltage Warning"
Q1: library part "BC848CLT1G, ON Semiconductor", "Transistor, NPN, 30 V, 0.1 A, SOT-23"
R1 R6 R26: "RES, 10, 5%, 0.063 W, 0402"
R3 R10 R15 R22 R27 R32: "RES, 1.0 k, 5%, 0.125 W, 0805"
R4 R11 R18 R23 R28 R33: "RES, 4.99 k, 1%, 0.063 W, 0402"
R5 R12 R19 R24 R29 R34: "RES, 4.7, 5%, 0.33 W, 1206"
R7 R14 R20 R25 R30 R35: "RES, 4.7, 5%, 0.25 W, 0805"
R8 R21 R31: library part CRCW040210R0JNED, "RES, 10, 5%, 0.063 W, 0402"
R9: "RES, 22 k, 5%, 0.1 W, 0603"
R13 R36: "RES, 100 k, 5%, 0.1 W, 0603"
R16 R17: library part CRCW040210K0JNED, "RES, 10 k, 5%, 0.063 W, 0402"
T1 T2 T3 T4 T5 T6: "Transformer, 50 uH, SMT"
U1 U3 U5 U7 U9 U11: "LOW-NOISE 1A TRANSFORMER DRIVERS FOR ISOLATED POWER SUPPLIES, DBV0006A"
U2 U4 U6 U8 U10 U12: "High-CMTI 2.5-A / 5-A Isolated IGBT, MOSFET Gate Driver with Active Safety Features, DW0016B"
U13: "150-mA, 6.5-V, 1-uA IQ Voltage Regulators with Enable, DRV0006A"
ZZ2 ZZ3 ZZ4: library part AssemblyNote

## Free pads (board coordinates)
  oval 19x500 hole 20 slot 500 at 90 deg unplated mask+10: 0(782,425) 0(790.49,5006.51) 0(792.49,3166.51) 0(793,1326) 0(796.49,2249.51) 0(797.49,4098.51)

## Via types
v1: diameter 32, hole 16, Top Layer to Bottom Layer, 85 vias
v2: diameter 24, hole 12, Top Layer to Bottom Layer, 30 vias
v3: diameter 40, hole 20, Top Layer to Bottom Layer, 12 vias
v4: diameter 19.68, hole 7.87, Top Layer to Bottom Layer, 2 vias

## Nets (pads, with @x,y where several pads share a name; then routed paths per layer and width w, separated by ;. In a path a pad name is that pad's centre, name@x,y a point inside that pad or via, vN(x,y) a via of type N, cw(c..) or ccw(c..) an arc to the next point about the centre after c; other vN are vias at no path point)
\FAULT: C9.1 C18.1 C32.1 C42.1 C52.1 C62.1 J2.1 R17.1 U2.13 U4.13 U6.13 U8.13 U10.13 U12.13 | length 7245.7
  Top Layer w10: v2@233,4144.5 233,4954 v2(267,4988) ; v2(239,474) v2(239,1374) ; R17.1@330.38,2515 296,2515 J2.1@240,2459 ; v2(334,3213) 318,3229 230,3229 v2(226,3225) 226,3140 299,3067 299,2637 264,2602 207,2602 190,2585 190,2509 J2.1@240,2459 ; v2(339,2283) 261,2283 240,2304 J2.1@240,2459
  Bottom Layer w10: v2@234,3229 234,4140.5 v2(235.5,4142) 240.01,4146.51 508.11,4146.51 C62.1@533.11,4121.51 U12.13@609.48,4121.51 ; v2(239,474) 493.62,474 C18.1@518.62,449 U4.13@594.99,449 ; J2.1@240,2459 240,1375 v2(239,1374) 503.62,1374 C9.1@528.62,1349 U2.13@604.99,1349 ; v2(267,4988) 333.51,5054.51 501.11,5054.51 C52.1@526.11,5029.51 U10.13@602.48,5029.51 ; v2(334,3213) 357,3236 522,3236 528.11,3229.89 C32.1@528.11,3199.51 U6.13@604.48,3199.51 ; v2(339,2283) 353.32,2297.32 506.92,2297.32 507.11,2297.51 C42.1@532.11,2272.51 U8.13@608.48,2272.51
\RESET: J2.5 U2.14 U4.14 U6.14 U8.14 U10.14 U12.14 | length 6837.7
  Top Layer w10: v2(206,4172) 206,4983 225,5002 v2(225,5005) ; J2.5@240,2659 189,2710 189,3249 v2(204,3264) 211,3257 v2(326,3257) ; v2(264,500) 269,505 v2(269,1420) ; v2(265,2382) 268,2382 v2(329,2321)
  Bottom Layer w10: v2(204,3264) 206.5,3266.5 v2@206.5,4170 ; v2(206,4172) 206.5,4171.5 v2@206.5,4170 ; v2(225,5005) 225,5002 303,5080 601.99,5080 U10.14@602.48,5079.51 ; J2.5@240,2659 240,2654 284,2610 284,2401 v2(265,2382) 267,2380 267,1422 v2(269,1420) 290,1399 U2.14@604.99,1399 ; v2(264,500) 265,499 U4.14@594.99,499 ; v2(326,3257) 329,3254 599.99,3254 U6.14@604.48,3249.51 ; v2@330.51,2322.51 U8.14@608.48,2322.51 ; U12.14@609.48,4171.51 607.97,4170 v2@206.5,4170
COLLECTOR_B_U: D8.1 J4.3 | length 121.9
  Bottom Layer w30: D8.1@1477.74,570 1596.37,570 J4.3@1598.69,567.68
COLLECTOR_B_V: D22.1 J6.3 | length 116.1
  Bottom Layer w30: D22.1@1483.74,2486 1596,2486 J6.3@1598.69,2488.69
COLLECTOR_B_W: D34.1 J8.3 | length 117.3
  Bottom Layer w30: D34.1@1492.23,4292.51 1572.51,4292.51 J8.3@1598.69,4318.69
COLLECTOR_T_U: D2.1 J3.3 | length 120.6
  Bottom Layer w30: D2.1@1478.74,1560 1597,1560 J3.3@1598.69,1561.68
COLLECTOR_T_V: D15.1 J5.3 | length 117.1
  Bottom Layer w30: D15.1@1484.74,3428 1601.37,3428 J5.3@1601.69,3427.68
COLLECTOR_T_W: D28.1 J7.3 | length 126.6
  Bottom Layer w30: D28.1@1478.61,5225 1494.29,5240.69 J7.3@1598.69,5240.69
E\N\A\B\L\E\: J2.7 R13.1 | length 123.7
  Bottom Layer w10: J2.7@240,2759 275,2759 310.5,2723.5 R13.1@349,2723.5
ENABLE: Q1.3 R9.1 U1.5 U3.5 U5.5 U7.5 U9.5 U11.5 U13.4 | length 5701.2
  Top Layer w10: v2(313,2251) 319,2257 U7.5@383.87,2257 412,2257 444,2225 444,2090 294,1940 294,1358 318,1334 ; U3.5@369.87,434 320,434 289,465 289,1305 318,1334 ; U9.5@377.36,5014.51 315.5,5014.51 294,4993.01 294,4145 329,4110 ; U5.5@379.36,3184.51 330.48,3184.51 320.48,3174.52 307.49,3161.52 307.49,3130.89 348.38,3090 348.38,2690.62 v2(404,2635) ; U1.5@379.87,1334 318,1334 ; U11.5@384.87,4110 329,4110 ; U13.4@554.59,3753.39 554.59,3839.41 459,3935 v2(329,3935) 324,3935 304,3955 304,4085 329,4110
  Bottom Layer w10: v2(313,2251) 304,2260 304,2360.19 320,2376.19 320,2551 v2(404,2635) 405.26,2633.74 448.57,2633.74 R9.1@449,2634.17 ; v2(318,3177) 309,3186 309,3238.64 301,3246.64 301,3907 v2(329,3935) ; Q1.3@449,2692.76 R9.1@449,2634.17 ; R9.1@449.94,2635.12 R9.1@449,2634.17
GATE_B_U: C24.1 J4.2 R12.2 R14.2 U4.7 | length 879.6
  Bottom Layer w20: U4.7@969.01,299 1035,299 1053,281 1053,249
  Bottom Layer w25: 1053,249 1053,164 1073,144 1175,144 1232.09,201.09 R12.2@1232.09,213 1323,213 R14.2@1324,214 ; J4.2@1598.69,367.18 J4.2@1598.69,367.68
  Bottom Layer w35: R14.2@1325,211 1413,211 1440,238 1440,267 1466.5,293.5 C24.1@1525,293.5 J4.2@1598.69,367.18
GATE_B_V: C40.1 J6.2 R24.2 R25.2 U8.7 | length 969
  Bottom Layer w20: U8.7@982.5,2122.51 1048.49,2122.51 1062,2109 1062,2067
  Bottom Layer w25: 1062,2067 1062,1988 1090,1960 1187,1960 1243.09,2016.09 R24.2@1243.09,2028 1332,2028 R25.2@1333,2029
  Bottom Layer w30: C40.1@1521,2215.5 C40.1@1525.5,2215.5
  Bottom Layer w35: R25.2@1333,2029 1411,2029 1434,2052 1434,2174 1475.5,2215.5 C40.1@1521,2215.5 ; C40.1@1525.5,2215.5 J6.2@1598.69,2288.69
GATE_B_W: C60.1 J8.2 R34.2 R35.2 U12.7 | length 933.9
  Bottom Layer w20: U12.7@983.5,3971.51 1049.49,3971.51 1063,3958 1063,3931
  Bottom Layer w25: 1063,3931 1063,3840 1090,3813 1184,3813 R34.2@1241.09,3870.09 ; R34.2@1245.09,3881 1331,3881 R35.2@1332,3880
  Bottom Layer w35: R35.2@1332,3880 1400,3880 1431,3911 1431,4022 1455.5,4046.5 C60.1@1515,4046.5 1526.5,4046.5 J8.2@1598.69,4118.69
GATE_T_U: C22.1 J3.2 R5.2 R7.2 U2.7 | length 956.6
  Bottom Layer w20: U2.7@979.01,1199 1045,1199 1063,1181 1063,1142
  Bottom Layer w25: 1063,1142 1063,1065 1081,1047 1182,1047 1238.09,1103.09 R5.2@1238.09,1114 1327,1114 R7.2@1329,1112 ; J3.2@1598.69,1356.18 J3.2@1598.69,1361.68
  Bottom Layer w35: R7.2@1329,1112 1417,1112 1444,1139 1444,1249 1476.5,1281.5 C22.1@1524,1281.5 J3.2@1598.69,1356.18
GATE_T_V: C30.1 J5.2 R19.2 R20.2 U6.7 | length 977.4
  Bottom Layer w20: U6.7@978.5,3049.51 1044.49,3049.51 1060,3034 1060,2999
  Bottom Layer w25: 1060,2999 1060,2923 1091,2892 1192,2892 1261,2961 R20.2@1337,2961 ; J5.2@1594.19,3227.68 J5.2@1601.69,3227.68
  Bottom Layer w35: R20.2@1337,2961 1406,2961 1427,2982 1427,3127 1453.5,3153.5 C30.1@1520,3153.5 J5.2@1594.19,3227.68
GATE_T_W: C50.1 J7.2 R29.2 R30.2 U10.7 | length 956.9
  Bottom Layer w20: U10.7@976.5,4879.51 1027.49,4879.51 1058,4849 ; R29.2@1258.09,4780.09 R29.2@1258.09,4793
  Bottom Layer w25: 1058,4849 1058,4737 1075,4720 1198,4720 R29.2@1258.09,4780.09
  Bottom Layer w30: R29.2@1258.09,4793 R30.2@1357,4793 ; J7.2@1598.19,5040.69 J7.2@1598.69,5040.69
  Bottom Layer w35: R30.2@1357,4793 1408,4793 1435,4820 1435,4927 1469.5,4961.5 C50.1@1519,4961.5 J7.2@1598.19,5040.69
GND: C1.1 C2.2 C5.1 C6.2 C8.2 C9.2 C10.1 C11.2 C15.2 C17.2 C18.2 C19.2 C20.2 C26.2 C27.2 C31.2 C32.2 C33.1 C34.2 C37.2 C41.2 C42.2 C43.1 C46.2 C47.2 C51.2 C52.2 C53.1 C54.2 C57.2 C61.2 C62.2 C63.2 J1.1 J2.9 J2.11 Q1.2 R36.1 U1.4 U1.6 U2.9 U2.11 U2.16 U3.4 U3.6 U4.9 U4.11 U4.16 U5.4 U5.6 U6.9 U6.11 U6.16 U7.4 U7.6 U8.9 U8.11 U8.16 U9.4 U9.6 U10.9 U10.11 U10.16 U11.4 U11.6 U12.9 U12.11 U12.16 U13.3 U13.7 | length 5365.9
  Top Layer w12: U13.3@554.59,3676.61 554.59,3660.68 563,3652.27 563,3627.5 C20.2@560.5,3625
  Top Layer w15: v1(314,2213) 318,2213 327,2222 379.25,2222 379.76,2222.51 382.76,2219.51 U7.6@383.36,2220.11 ; v1(317,399) 366.27,399 369.27,396 U3.6@369.87,396.6 ; v1(323,4981) 324.49,4979.51 373.76,4979.51 376.76,4976.51 U9.6@377.36,4977.11 ; v1(329,1299) 376.27,1299 379.27,1296 U1.6@379.87,1296.6 ; v1(333,4071) 380.25,4071 380.76,4071.51 383.76,4068.51 U11.6@384.36,4069.11 ; U5.6@379.36,3147.11 379.36,3116.64 v2(380,3116)
  Top Layer w20: v1(318,594) 319,595 C10.1@363.5,595 363.5,534 C15.2@365.5,532 369.87,527.64 U3.4@369.87,471.4 ; v1(328,1494) 329,1495 C1.1@373.5,1495 373.5,1434 C6.2@375.5,1432 379.87,1427.64 U1.4@379.87,1371.4 ; v1(332.49,4266.51) 333.49,4267.51 C53.1@377.99,4267.51 377.99,4206.51 C57.2@379.99,4204.51 384.36,4200.15 U11.4@384.36,4143.91 ; v1(364,3392) 369,3392 372,3389 374.5,3386.48 C5.1@374.5,3345 ; C43.1@370.99,5175.51 370.99,5114.51 C47.2@372.99,5112.51 377.36,5108.15 U9.4@377.36,5051.91 ; C43.1@372.5,5175 372.5,5223.5 v1(374,5225) ; C5.1@372.99,3345 372.99,3284.51 C27.2@374.99,3282.51 382,3275.5 382,3224.56 U5.4@379.36,3221.91 ; v1(379,2465) 379,2420.52 C33.1@376.99,2418.51 376.99,2357.51 C37.2@378.99,2355.51 378.99,2299.27 U7.4@383.87,2294.4
  Bottom Layer w15: v1(314,2213) 318,2213 321.51,2216.51 C41.2@485.87,2216.51 ; v1(317,399) 323,393 C17.2@472.38,393 ; v1(323,4981) 333,4981 340.49,4973.51 C51.2@479.87,4973.51 ; v1(329,1299) 335,1293 C8.2@482.38,1293 ; v1(333,4071) 338.49,4065.51 C61.2@486.87,4065.51 ; v2(380,3116) 407.51,3143.51 C31.2@481.87,3143.51 ; C17.2@471.38,394 C18.2@471.38,449 ; C51.2@478.87,4974.51 C52.2@478.87,5029.51 ; C31.2@480.87,3144.51 C32.2@480.87,3199.51 ; C8.2@481.38,1294 C9.2@481.38,1349 ; C41.2@484.87,2217.51 C42.2@484.87,2272.51 ; C61.2@485.87,4066.51 C62.2@485.87,4121.51
  Bottom Layer w20: v1(381,2152) 502.98,2152 523.49,2172.51 U8.11@608.48,2172.51 ; v1(414,332) 493,332 510,349 U4.11@594.99,349 ; v1(421.49,4912.51) 500.49,4912.51 517.49,4929.51 U10.11@602.48,4929.51 ; v1(423.49,3082.51) 502.49,3082.51 519.49,3099.51 U6.11@604.48,3099.51 ; v1(424,1232) 503,1232 520,1249 U2.11@604.99,1249 ; v1(455,4004.51) 507.49,4004.51 524.49,4021.51 U12.11@609.48,4021.51 ; C17.2@471.38,394 C17.2@472.38,393 ; C51.2@478.87,4974.51 C51.2@479.87,4973.51 ; R36.1@480.5,2905 480.5,2876.5 472.62,2868.62 C63.2@472.62,2845 472.62,2811.38 486.4,2797.6 Q1.2@486.4,2787.24 522.76,2787.24 v1(523,2787) ; C31.2@480.87,3144.51 C31.2@481.87,3143.51 ; C8.2@481.38,1294 C8.2@482.38,1293 ; C41.2@484.87,2217.51 C41.2@485.87,2216.51 ; C61.2@485.87,4066.51 C61.2@486.87,4065.51 ; v1(516,1555) 517,1554 C2.2@517,1510.5 546.77,1510.5 558.27,1499 U2.16@604.99,1499 ; v1(520.49,4327.51) 521.49,4326.51 C54.2@521.49,4283.01 551.26,4283.01 562.76,4271.51 U12.16@609.48,4271.51 ; v1(527,3418) 527,3417.02 515.49,3405.51 516.49,3404.51 C26.2@516.49,3361.01 546.26,3361.01 557.76,3349.51 U6.16@604.48,3349.51 ; v1(529,4831) 530.49,4829.51 U10.9@602.48,4829.51 U10.9@601,4828.03 ; v1(531,3921) 531.51,3921.51 U12.9@609.48,3921.51 ; v1(532,249) U4.9@594.99,249 ; v1(532,1149) U2.9@604.99,1149 ; v1(539.51,2999.51) U6.9@604.48,2999.51 ; v1(540,681) 534,681 507,654 C11.2@507,610.5 536.77,610.5 548.27,599 U4.16@594.99,599 ; v1(546,5261) 540.98,5261 514.49,5234.51 C46.2@514.49,5191.01 544.26,5191.01 555.76,5179.51 U10.16@602.48,5179.51 ; v1(547,2073) 547.49,2072.51 U8.9@608.48,2072.51 ; v1(554,2484) v1@554,2484.53 ; v1@557.46,2488 v1@554,2484.53 ; U8.16@608.48,2422.51 561.76,2422.51 550.26,2434.01 C34.2@520.49,2434.01 520.49,2451.02 v1@554,2484.53
  other v3: 344,3455 404,3455
  other v4: 507.35,3715 550.65,3715
ISO_GND_BOT_U: C12.2 C13.2 C16.2 C23.2 C24.2 C65.2 D11.2 D12.2 J4.1 T2.5 U4.1 U4.3 U4.8 | length 644.8
  Top Layer w20: v1(990,170) 997,170 1025,198 D11.2@1064.47,198 ; T2.5@1004.64,434 1061,434 1080,415 1126,415
  GND w20: v1@1134,525 v1(1136,523)
  Bottom Layer w20: v1(969,213) U4.8@969.01,249 ; U4.1@969.01,599 1023,599 1029.62,605.62 C16.2@1057,605.62 v1(1057,646) 1082.31,671.31 D12.2@1127,671.31 ; C12.2@1067,465.5 1067,512 v1(1071,516)
  Bottom Layer w35: C24.2@1525,230.5 1525,184 1541.32,167.68 J4.1@1598.69,167.68
ISO_GND_BOT_V: C35.2 C36.2 C38.2 C39.2 C40.2 C67.2 D25.2 D26.2 J6.1 T4.5 U8.1 U8.3 U8.8 | length 596.4
  Top Layer w20: v1(1003.49,1993.51) 1010.49,1993.51 1038.49,2021.51 D25.2@1077.96,2021.51 ; T4.5@1018.13,2257.51 1069.49,2257.51 1091,2236 1139.49,2236
  Bottom Layer w20: v1(982.49,2036.51) U8.8@982.5,2072.51 ; U8.1@982.5,2422.51 1036.49,2422.51 1043.11,2429.13 C39.2@1070.49,2429.13 v1(1070.49,2469.51) 1094.29,2493.31 D26.2@1139,2493.31 ; C35.2@1080.49,2289.01 1079,2290.5 C35.2@1081,2292.5
  Bottom Layer w35: C40.2@1521,2152.5 1521,2109 1541.32,2088.69 J6.1@1598.69,2088.69
  other v1: 1084.49,2339.51 1164,2340
ISO_GND_BOT_W: C55.2 C56.2 C58.2 C59.2 C60.2 C69.2 D37.2 D38.2 J8.1 T6.5 U12.1 U12.3 U12.8 | length 648
  Top Layer w20: v1(1004.49,3842.51) 1011.49,3842.51 1039.49,3870.51 D37.2@1078.96,3870.51 ; T6.5@1019.13,4106.51 1070.49,4106.51 1092,4085 1140.49,4085
  Bottom Layer w20: v1(983.49,3885.51) U12.8@983.5,3921.51 ; U12.1@983.5,4271.51 1037.49,4271.51 1044.11,4278.13 C59.2@1071.49,4278.13 v1(1071.49,4318.51) 1093.29,4340.31 D38.2@1139,4340.31 ; v1@1081,4188 1081,4138.5 C55.2@1081.49,4138.01
  Bottom Layer w35: C60.2@1515,3983.5 1515,3937 1533.32,3918.69 J8.1@1598.69,3918.69
  other v1: 1160,4188 1085.49,4188.51
ISO_GND_TOP_U: C3.2 C4.2 C7.2 C21.2 C22.2 C64.2 D5.2 D6.2 J3.1 T1.5 U2.1 U2.3 U2.8 | length 636.4
  Top Layer w20: v1(1000,1070) 1007,1070 1035,1098 D5.2@1074.47,1098 ; T1.5@1014.64,1334 1066,1334 1087,1313 1136,1313
  Bottom Layer w20: v1(979,1113) U2.8@979.01,1149 ; U2.1@979.01,1499 1033,1499 1039.62,1505.62 C7.2@1067,1505.62 v1(1067,1546) 1089.31,1568.31 D6.2@1135,1568.31 ; C3.2@1077,1365.5 1077,1412 v1(1081,1416)
  Bottom Layer w35: C22.2@1524,1218.5 1524,1175 1537.32,1161.68 J3.1@1598.69,1161.68
  other v1: 1159,1419
ISO_GND_TOP_V: C14.2 C25.2 C28.2 C29.2 C30.2 C66.2 D19.2 D20.2 J5.1 T3.5 U6.1 U6.3 U6.8 | length 646.2
  Top Layer w20: v1(999.49,2920.51) 1006.49,2920.51 1034.49,2948.51 D19.2@1073.96,2948.51 ; T3.5@1014.13,3184.51 1065.49,3184.51 1087,3163 1135.49,3163
  Bottom Layer w20: v1(978.49,2963.51) U6.8@978.5,2999.51 ; U6.1@978.5,3349.51 1032.49,3349.51 1039.11,3356.13 C29.2@1066.49,3356.13 v1(1066.49,3396.51) 1089.29,3419.31 D20.2@1134,3419.31 ; C14.2@1076.49,3216.01 1079,3218.52 v1@1079,3267
  Bottom Layer w35: C30.2@1520,3090.5 1520,3046 1538.32,3027.68 J5.1@1601.69,3027.68
  other v1: 1080.49,3266.51 1161,3268
ISO_GND_TOP_W: C44.2 C45.2 C48.2 C49.2 C50.2 C68.2 D31.2 D32.2 J7.1 T5.5 U10.1 U10.3 U10.8 | length 630.7
  Top Layer w20: v1(997.49,4750.51) 1004.49,4750.51 1032.49,4778.51 D31.2@1071.96,4778.51 ; T5.5@1012.13,5014.51 1063.49,5014.51 1085,4993 1133.49,4993
  Bottom Layer w20: v1(976.49,4793.51) U10.8@976.5,4829.51 ; U10.1@976.5,5179.51 1030.49,5179.51 1037.11,5186.13 C49.2@1064.49,5186.13 v1(1064.49,5226.51) 1076.29,5238.31 D32.2@1131,5238.31 ; C44.2@1074.49,5046.01 1074,5046.5 1075,5047.5 v1@1075,5098
  Bottom Layer w35: C50.2@1519,4898.5 1519,4865 1543.32,4840.69 J7.1@1598.69,4840.69
  other v1: 1078.49,5096.51 1157,5097
NetC7_1: C7.1 D6.1 R3.1 U2.2 | length 257.1
  Bottom Layer w20: U2.2@979.01,1449 1026,1449 1035.38,1458.38 C7.1@1067,1458.38 1091.38,1458.38 1114.69,1481.69 D6.1@1135,1481.69 1220.69,1481.69 R3.1@1222,1483
NetC16_1: C16.1 D12.1 R10.1 U4.2 | length 266.3
  Bottom Layer w20: U4.2@969.01,549 1016,549 1025.38,558.38 C16.1@1057,558.38 1081.38,558.38 1107.69,584.69 D12.1@1127,584.69 1155,584.69 1168,571.69 1204.31,571.69 R10.1@1212,564
NetC29_1: C29.1 D20.1 R15.1 U6.2 | length 258.3
  Bottom Layer w20: U6.2@978.5,3299.51 1025.49,3299.51 1034.87,3308.89 C29.1@1066.49,3308.89 1090.87,3308.89 1114.67,3332.69 D20.1@1134,3332.69 1215.31,3332.69 R15.1@1219,3329 ; R15.1@1219,3314.51 R15.1@1221.49,3314.51
NetC39_1: C39.1 D26.1 R22.1 U8.2 | length 259.6
  Bottom Layer w20: U8.2@982.5,2372.51 1029.49,2372.51 1038.87,2381.89 C39.1@1070.49,2381.89 1094.87,2381.89 1119.67,2406.69 D26.1@1139,2406.69 1224.69,2406.69 R22.1@1227,2409
NetC49_1: C49.1 D32.1 R27.1 U10.2 | length 252.5
  Bottom Layer w20: U10.2@976.5,5129.51 1023.49,5129.51 1032.87,5138.89 C49.1@1064.49,5138.89 1088.87,5138.89 1111.67,5161.69 D32.1@1134,5161.69 1135.69,5160 R27.1@1215,5160
NetC59_1: C59.1 D38.1 R32.1 U12.2 | length 257.9
  Bottom Layer w20: U12.2@983.5,4221.51 1030.49,4221.51 1039.87,4230.89 C59.1@1071.49,4230.89 1116.2,4230.89 D38.1@1139,4253.69 1220.31,4253.69 R32.1@1224,4250 ; R32.1@1224,4236.51 R32.1@1226.49,4236.51
NetC63_1: C63.1 Q1.1 R13.2 R36.2 | length 189.6
  Bottom Layer w10: R13.2@349,2786.5 410.85,2786.5 410.85,2796.85 425.38,2811.38 C63.1@425.38,2845 425.38,2867.42 417.5,2875.3 R36.2@417.5,2905
NetD1_2: D1.2 T1.4 | length 114.1
  Top Layer w20: T1.4@1014.64,1213.92 1073.61,1213.92 D1.2@1107.53,1180 ; D1.2@1105.03,1177.5 1106.53,1176 D1.2@1106.53,1171
NetD2_2: D2.2 R3.2 | length 100.5
  Bottom Layer w20: R3.2@1222,1563 1225,1560 D2.2@1321.26,1560
NetD3_2: D3.2 T1.6 | length 106.2
  Top Layer w20: T1.6@1014.64,1454.08 1068.61,1454.08 D3.2@1105.53,1491
NetD4_1: D4.1 R5.1 U2.6 | length 302.8
  Bottom Layer w20: 1019.57,1249 U2.6@979.01,1249 1040,1249 1074,1215 D4.1@1125.53,1215
  Bottom Layer w25: R5.1@1123.91,1114 1125.53,1115.62 D4.1@1125.53,1215
NetD4_2: D4.2 R7.1
NetD5_1: D5.1 R4.1 | length 54.9
  Top Layer w20: D5.1@1133.53,1098 R4.1@1188.38,1098
NetD7_2: D7.2 T2.4 | length 114.1
  Top Layer w20: T2.4@1004.64,313.92 1063.61,313.92 D7.2@1097.53,280 ; D7.2@1095.03,277.5 1096.53,276 D7.2@1096.53,271
NetD8_2: D8.2 R10.2 | length 168.6
  Bottom Layer w30: R10.2@1212,644 1297,644 1320.26,620.74 D8.2@1320.26,570
NetD9_2: D9.2 T2.6 | length 106.2
  Top Layer w20: T2.6@1004.64,554.08 1058.61,554.08 D9.2@1095.53,591
NetD10_1: D10.1 R12.1 U4.6 | length 266.7
  Bottom Layer w20: U4.6@969.01,349 1030,349 1065,314 D10.1@1119.53,314
  Bottom Layer w25: R12.1@1117.91,213 1119.53,214.62 D10.1@1119.53,314
NetD10_2: D10.2 R14.1
NetD11_1: D11.1 R11.1 | length 54.9
  Top Layer w20: D11.1@1123.53,198 R11.1@1178.38,198
NetD13_2: D13.2 J1.2
NetD14_2: D14.2 T3.4 | length 114.1
  Top Layer w20: T3.4@1014.13,3064.43 1073.1,3064.43 D14.2@1107.02,3030.51 ; D14.2@1104.52,3028.01 1106.02,3026.51 D14.2@1106.02,3021.51
NetD15_2: D15.2 R15.2 | length 108.9
  Bottom Layer w25: R15.2@1219,3409 1322.26,3409 D15.2@1326.26,3413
